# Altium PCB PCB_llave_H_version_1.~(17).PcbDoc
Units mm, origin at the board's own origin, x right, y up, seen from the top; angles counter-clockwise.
Board outline 232.16 x 155.45 mm, 2 copper layers (Top Layer, Bottom Layer); 49 components, 32 nets, 153 pads, 0 vias.
Unrouted connection lines stored in the file: 50.
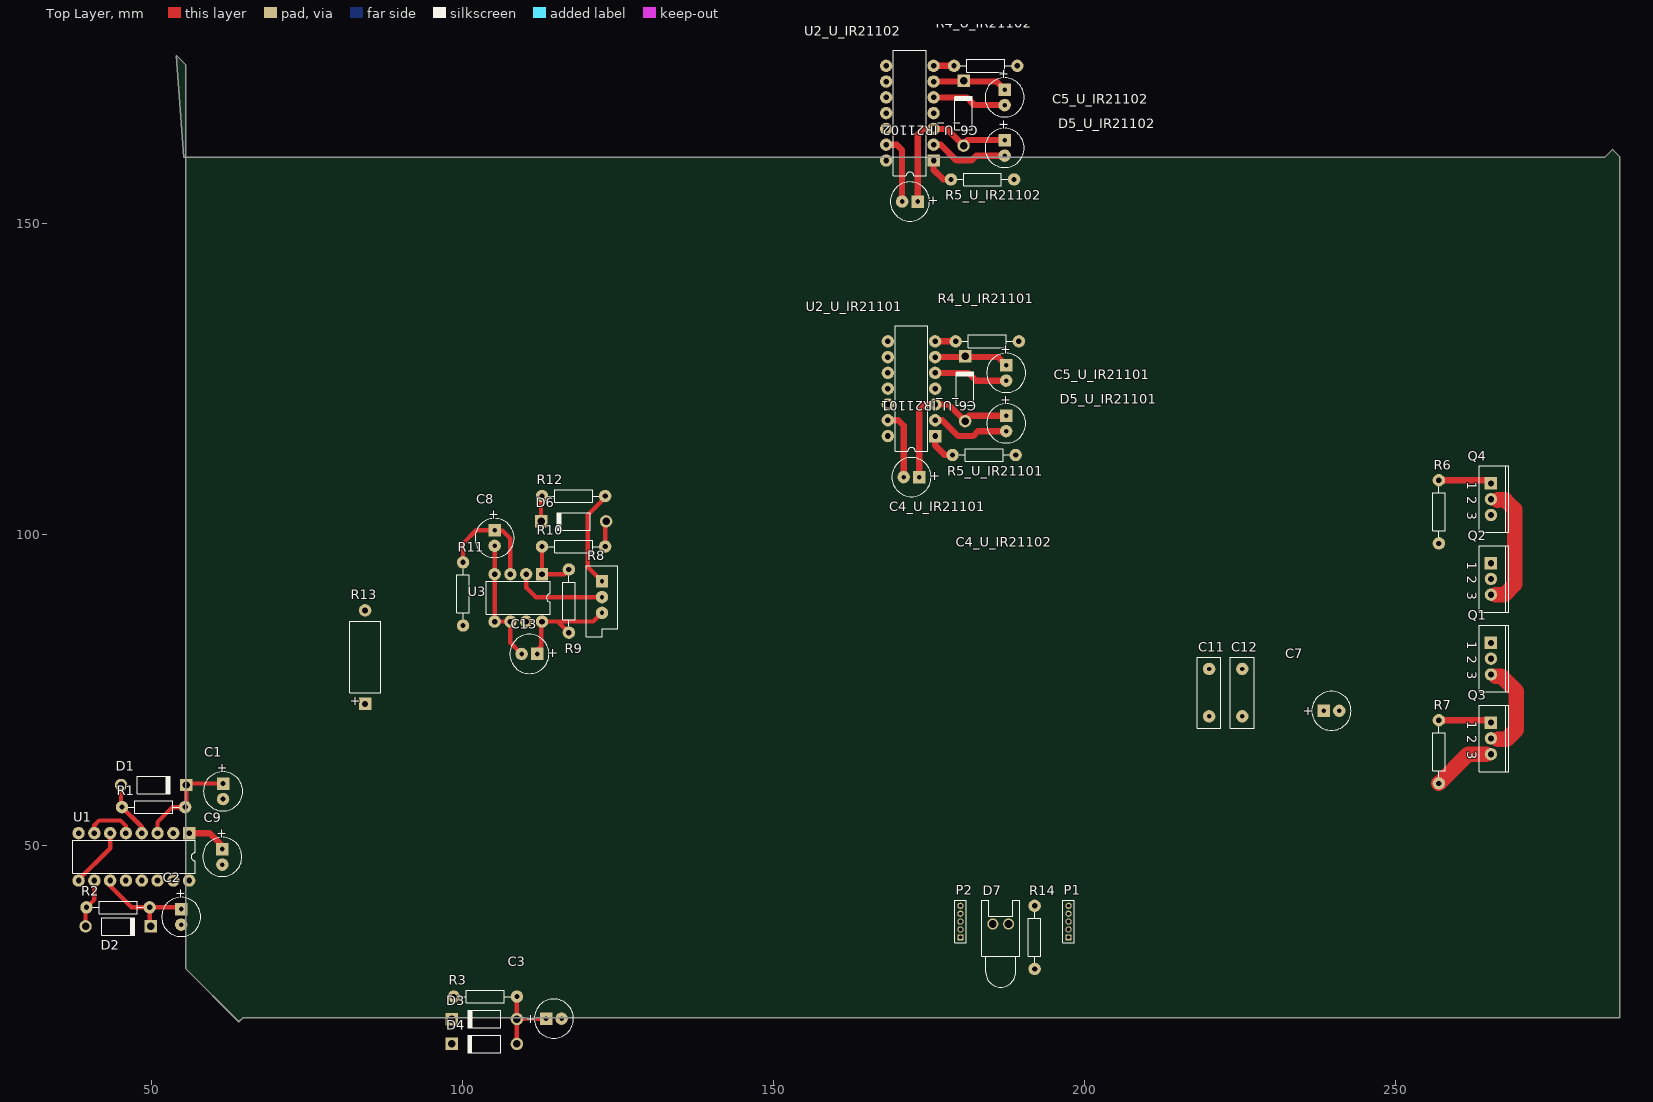
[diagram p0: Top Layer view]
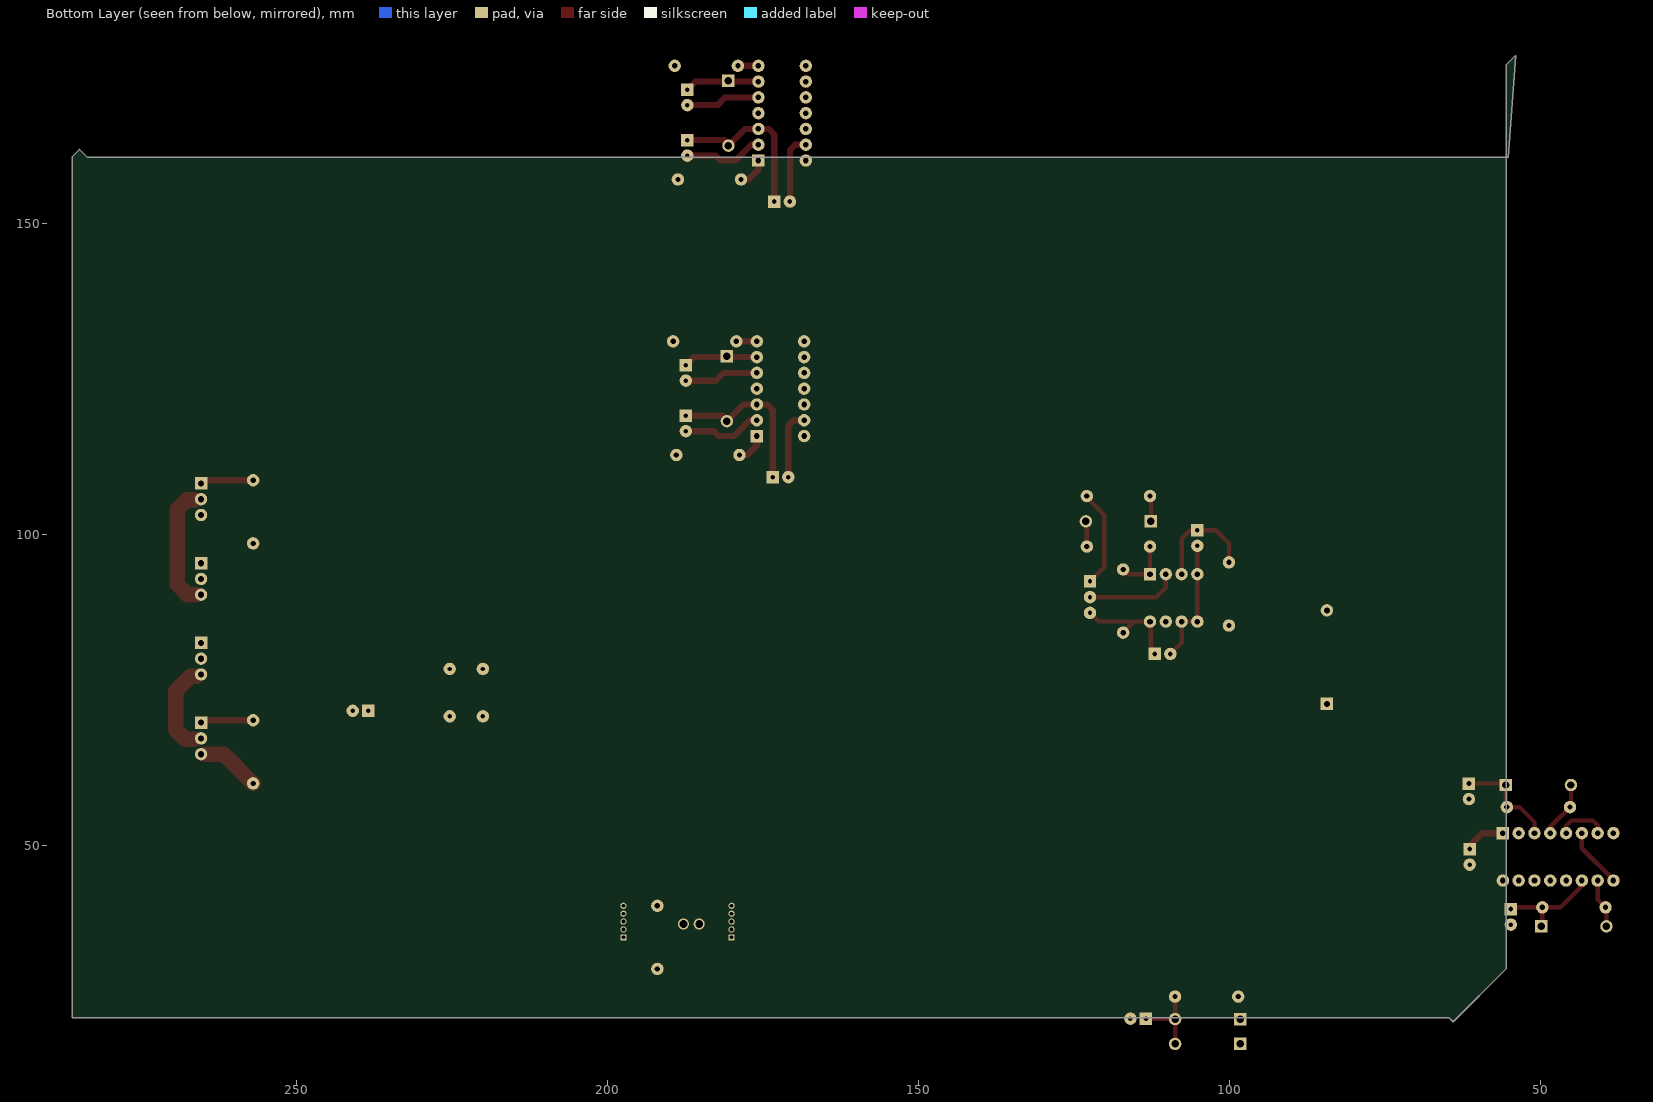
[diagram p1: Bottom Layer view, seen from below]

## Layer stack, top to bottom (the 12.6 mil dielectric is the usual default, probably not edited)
Top Layer: signal copper 0.0356
Dielectric: dielectric 0.32, FR-4, Dk 4.8
Bottom Layer: signal copper 0.0356

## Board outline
53.975,177.038 55.499,175.514 55.499,30.099 64.008,21.59 64.643,22.225 286.131,22.225 286.131,160.782 284.988,161.925 283.718,160.655 55.118,160.655

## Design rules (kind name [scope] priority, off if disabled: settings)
Clearance [All] p1: gap=0.4
ComponentClearance [All] p1: gap=0.254 collisioncheckmode=2 verticalgap=0.254
PolygonConnect [All] p1: connectstyle=Relief reliefconductorwidth=0.254 reliefentries=4 polygonreliefangle="90 Angle"
RoomDefinition U_IR21102 [InComponentClass('U_IR21102')] p1: confinementstyle=ConfineIn formatcopy=TRUE lockcomponents=FALSE outline 164.846,185.293 191.643,185.293 191.643,145.161 164.846,145.161
RoomDefinition U_INITShutdown [InComponentClass('U_INITShutdown')] p2: confinementstyle=ConfineIn formatcopy=TRUE lockcomponents=FALSE outline 90.297,32.893 141.097,32.893 141.097,13.97 90.297,13.97
RoomDefinition U_Shutdown [InComponentClass('U_Shutdown')] p3: confinementstyle=ConfineOut formatcopy=TRUE lockcomponents=FALSE outline 65.913,145.923 116.713,145.923 116.713,121.92 65.913,121.92
RoomDefinition Llave_H_esquema [InComponentClass('Llave_H_esquema')] p4: confinementstyle=ConfineIn formatcopy=TRUE lockcomponents=FALSE outline 178.943,26.924 199.263,26.924 199.263,43.942 178.943,43.942
RoomDefinition U_4049 [InComponentClass('U_4049')] p5: confinementstyle=ConfineIn formatcopy=TRUE lockcomponents=FALSE outline 27.813,33.147 69.469,33.147 69.469,65.913 27.813,65.913
RoomDefinition U_IR21101 [InComponentClass('U_IR21101')] p6: confinementstyle=ConfineIn formatcopy=TRUE lockcomponents=FALSE outline 165.1,140.97 191.897,140.97 191.897,100.838 165.1,100.838
RoomDefinition U_Puente_H [InComponentClass('U_Puente_H')] p7: confinementstyle=ConfineOut formatcopy=TRUE lockcomponents=FALSE outline 178.943,93.853 183.134,93.853 183.134,85.09 178.943,85.09
RoutingVias [All] p1: holewidth=0.711 width=1.27 viastyle="Through Hole" minholewidth=0.711 minwidth=1.27 maxholewidth=0.711 maxwidth=1.27
SolderMaskExpansion [All] p1: expansion=0.102
TestPointUsage [All] p1: valid=0 allowmultiple=FALSE
Testpoint [All] p1: side=15 testpointundercomponent=TRUE minsize=1.016 maxsize=2.54 preferedsize=1.524 minholesize=0 maxholesize=1.016 preferedholesize=0.813 testpointgrid=0.025 style=1023 order=0-112345678
Width [All] p1: maxlimit=3 minlimit=0.7 preferedwidth=1
18 further rules are at their usual default settings.

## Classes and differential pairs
component class U_INITShutdown: C3 D3 D4 R3
channel class IR2110: U_IR21101 U_IR21102
component class U_Shutdown: C8 C13 D6 R8 R9 R10 R11 R12 R13 U3
component class U_Puente_H: C7 C11 C12 Q1 Q2 Q3 Q4 R6 R7
component class U_IR21102: C4_U_IR21102 C5_U_IR21102 C6_U_IR21102 D5_U_IR21102 R4_U_IR21102 R5_U_IR21102 U2_U_IR21102
component class U_IR21101: C4_U_IR21101 C5_U_IR21101 C6_U_IR21101 D5_U_IR21101 R4_U_IR21101 R5_U_IR21101 U2_U_IR21101
component class U_4049: C1 C2 C9 D1 D2 R1 R2 U1
component class Llave_H_esquema: D7 P1 P2 R14

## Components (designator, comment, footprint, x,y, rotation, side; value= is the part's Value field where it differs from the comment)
C1 "Cap Pol1" CAPPR2.5-6.3X5 61.468,58.674 r270 top
C2 "Cap Pol1" CAPPR2.5-6.3X5 54.737,38.481 r270 top
C3 "Cap Pol1" CAPPR2.5-6.3X5 114.681,22.098 r0 top
C4_U_IR21101 "Cap Pol1" CAPPR2.5-6.3X5 172.212,109.22 r180 top (schematic designator C4)
C4_U_IR21102 "Cap Pol1" CAPPR2.5-6.3X5 171.958,153.543 r180 top (schematic designator C4)
C5_U_IR21101 "Cap Pol1" CAPPR2.5-6.3X5 187.452,125.984 r270 top (schematic designator C5)
C5_U_IR21102 "Cap Pol1" CAPPR2.5-6.3X5 187.198,170.307 r270 top (schematic designator C5)
C6_U_IR21101 "Cap Pol1" CAPPR2.5-6.3X5 187.452,117.856 r270 top (schematic designator C6)
C6_U_IR21102 "Cap Pol1" CAPPR2.5-6.3X5 187.198,162.179 r270 top (schematic designator C6)
C7 "Cap Pol1" CAPPR2.5-6.3X5 239.776,71.628 r0 top
C8 "Cap Pol1" CAPPR2.5-6.3X5 105.156,99.421 r270 top
C9 "Cap Pol1" CAPPR2.5-6.3X5 61.341,48.133 r270 top
C11 "Cap" RAD-0.3 220.091,74.549 r90 top
C12 "Cap" RAD-0.3 225.425,74.549 r90 top
C13 "Cap Pol1" CAPPR2.5-6.3X5 110.744,80.772 r180 top
D1 "Diode" DO-204AL 50.292,59.69 r0 top
D2 "Diode" DO-204AL 44.577,36.957 r0 top
D3 "Diode" DO-204AL 103.505,22.036 r180 top
D4 "Diode" DO-204AL 103.505,18.034 r180 top
D5_U_IR21101 "Diode" DO-204AL 180.848,123.444 r90 top (schematic designator D5)
D5_U_IR21102 "Diode" DO-204AL 180.594,167.767 r90 top (schematic designator D5)
D6 "Diode" DO-204AL 117.856,102.108 r180 top
D7 "LED0" LED-0 186.563,37.338 r0 top
P1 "MHDR1X5" MHDR1X5 197.485,35.179 r90 top
P2 "MHDR1X5" MHDR1X5 180.086,35.179 r90 top
Q1 "IRF3205" TO-220AB 265.43,80.01 r270 top
Q2 "IRF3205" TO-220AB 265.43,92.837 r270 top
Q3 "IRF3205" TO-220AB 265.43,67.183 r270 top
Q4 "IRF3205" TO-220AB 265.43,105.664 r270 top
R1 "Res2" AXIAL-0.4 50.292,56.134 r180 top
R2 "Res2" AXIAL-0.4 44.577,40.005 r0 top
R3 "Res2" AXIAL-0.4 103.661,25.654 r180 top
R4_U_IR21101 "Res2" AXIAL-0.4 184.404,131.064 r0 top (schematic designator R4)
R4_U_IR21102 "Res2" AXIAL-0.4 184.15,175.387 r0 top (schematic designator R4)
R5_U_IR21101 "Res2" AXIAL-0.4 183.896,112.776 r0 top (schematic designator R5)
R5_U_IR21102 "Res2" AXIAL-0.4 183.642,157.099 r0 top (schematic designator R5)
R6 "Res2" AXIAL-0.4 257.048,103.632 r90 top
R7 "Res2" AXIAL-0.4 257.048,65.024 r90 top
R8 "RPot" VR5 122.428,89.916 r270 top
R9 "Res2" AXIAL-0.4 117.094,89.281 r270 top
R10 "Res2" AXIAL-0.4 117.856,98.044 r0 top
R11 "Res2" AXIAL-0.4 100.076,90.424 r90 top
R12 "Res2" AXIAL-0.4 117.856,106.172 r180 top
R13 "Res2" CAPPA15.05-11.5x5 84.328,80.264 r90 top
R14 "Res2" AXIAL-0.4 192.024,35.179 r90 top
U1 "MC54HC4049J" 620-09 47.117,48.133 r180 top
U2_U_IR21101 "IR2110" PDIP14 172.212,123.444 r90 top (schematic designator U2)
U2_U_IR21102 "IR2110" PDIP14 171.958,167.767 r90 top (schematic designator U2)
U3 "LM393N" 626-05 108.966,89.789 r180 top

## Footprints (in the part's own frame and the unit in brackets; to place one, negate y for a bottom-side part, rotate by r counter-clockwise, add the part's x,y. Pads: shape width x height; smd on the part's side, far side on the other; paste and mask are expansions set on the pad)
620-09 [mm] "DIP; 16 Leads; Row Spacing 7.62 mm; Pitch 2.54 mm"
  rect 2x2 hole 0.9: 1(-8.89,-3.81)
  round 2 hole 0.9: 2(-6.35,-3.81) 3(-3.81,-3.81) 4(-1.27,-3.81) 5(1.27,-3.81) 6(3.81,-3.81) 7(6.35,-3.81) 8(8.89,-3.81) 9(8.89,3.81) 10(6.35,3.81) 11(3.81,3.81) 12(1.27,3.81) 13(-1.27,3.81) 14(-3.81,3.81) 15(-6.35,3.81) 16(-8.89,3.81)
  silkscreen extent -9.85,-2.65 9.85,2.65
626-05 [mm] "DIP; 8 Leads; Row Spacing 7.62 mm; Pitch 2.54 mm"
  rect 2x2 hole 0.9: 1(-3.81,-3.81)
  round 2 hole 0.9: 2(-1.27,-3.81) 3(1.27,-3.81) 4(3.81,-3.81) 5(3.81,3.81) 6(1.27,3.81) 7(-1.27,3.81) 8(-3.81,3.81)
  silkscreen extent -5.15,-2.65 5.15,2.65
AXIAL-0.4 [mm] "Resistor; 2 Leads"
  round 2 hole 0.85: 1(-5.08,0) 2(5.08,0)
  silkscreen extent -4.06,-1.02 4.06,1.02
CAPPA15.05-11.5x5 [mm] "Capacitor, Electrolytic, Axial; Body 11.5 x 5 mm (LxDia. max), Lead Dia. 0.6 mm (typ)"
  rect 2x2 hole 0.95: 1(-7.525,0)
  round 2 hole 0.95: 2(7.525,0)
  silkscreen extent -5.75,-2.5 5.75,2.5
CAPPR2.5-6.3X5 [mm] "Capacitor, Electrolytic, Radial; Body 6.3 x 5 mm (Dia.xH typ); Pin Spacing 2.5 mm (typ)"
  rect 2x2 hole 0.75: 1(-1.25,0)
  round 2 hole 0.75: 2(1.25,0)
  silkscreen extent -3.15,-3.15 3.15,3.15
DO-204AL [mm] "Diode, Axial; Body 5.2 x 2.7 mm (LxDia. max), Lead Dia. 0.86 mm (max)"
  round 2 hole 1.2: 1(-5.23,0)
  rect 2x2 hole 1.2: 2(5.23,0)
  silkscreen extent -2.65,-1.4 2.75,1.4
LED-0 [mil] "Typical INFRARED GaAs LED; 2 Leads"
  round 70 hole 50: 1(50,0) 2(-50,0)
  silkscreen extent -120,-400 120,150
MHDR1X5 [mm] "Connector; Header; 5 Position"
  rect 1x1 hole 0.6: 1(0,0)
  round 1 hole 0.6: 2(1.27,0) 3(2.54,0) 4(3.81,0) 5(5.08,0)
  silkscreen extent -0.9,-0.9 5.98,0.9
PDIP14 [mm] "DIP; 14 Leads; Row Spacing 7.62 mm; Pitch 2.54 mm"
  rect 2x2 hole 0.9: 1(-7.62,-3.81)
  round 2 hole 0.9: 2(-5.08,-3.81) 3(-2.54,-3.81) 4(0,-3.81) 5(2.54,-3.81) 6(5.08,-3.81) 7(7.62,-3.81) 8(7.62,3.81) 9(5.08,3.81) 10(2.54,3.81) 11(0,3.81) 12(-2.54,3.81) 13(-5.08,3.81) 14(-7.62,3.81)
  silkscreen extent -10.1,-2.65 10.1,2.65
RAD-0.3 [mm] "Capacitor; 2 Leads"
  round 2 hole 0.7: 1(-3.81,0) 2(3.81,0)
  silkscreen extent -5.71,-1.91 5.71,1.91
TO-220AB [mm] "TO, Thru-Hole, Vertical, Heatsink Mounted; 3 In-Line Leads; Pitch 2.54 mm"
  rect 2x2 hole 1: 1(-2.54,0)
  round 2 hole 1: 2(0,0) 3(2.54,0)
  silkscreen extent -5.35,-1.85 5.35,2.85
VR5 [mm] "Potentiometer; 3 Leads"
  rect 2x2 hole 0.7: 1(-2.54,0)
  round 2 hole 0.7: 2(2.54,0) 3(0,0)
  silkscreen extent -5.08,-2.54 6.35,2.54

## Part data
C1 C2 C3 C4_U_IR21101 C4_U_IR21102 C5_U_IR21101 C5_U_IR21102 C6_U_IR21101 C6_U_IR21102 C7 C8 C9 C13: "Polarized Capacitor (Radial)"
C11 C12: "Capacitor"
D1 D2 D3 D4 D5_U_IR21101 D5_U_IR21102 D6: "Default Diode"
D7: "Typical INFRARED GaAs LED"
P1 P2: "Header, 5-Pin"
Q1 Q2 Q3 Q4: "HEXFET Power MOSFET"
R1 R2 R3 R4_U_IR21101 R4_U_IR21102 R5_U_IR21101 R5_U_IR21102 R6 R7 R9 R10 R11 R12 R13 R14: "Resistor"
R8: "Potentiometer"
U1: "Hex Inverting Buffer/Logic-Level Down Converter"
U2_U_IR21101 U2_U_IR21102: "High and Low Side Driver"
U3: "Dual Comparator"

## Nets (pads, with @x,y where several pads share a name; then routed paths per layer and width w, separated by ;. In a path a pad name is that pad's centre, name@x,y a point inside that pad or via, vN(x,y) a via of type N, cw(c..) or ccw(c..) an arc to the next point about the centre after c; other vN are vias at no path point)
COM_U_IR21101: C6_U_IR21101.2 C6_U_IR21102.2 Q3.3 Q4.3 R6.1 R7.1 R11.1 R13.2 U2_U_IR21101.2 U2_U_IR21102.2 | length 35.2
  Top Layer w1: U2_U_IR21102.2 176.911,162.687 179.451,160.147 181.864,160.147 182.646,160.929 C6_U_IR21102.2 ; U2_U_IR21101.2 177.165,118.364 179.705,115.824 182.118,115.824 182.9,116.606 C6_U_IR21101.2
  Top Layer w2.5: R7.1 261.747,64.643 Q3.3@264.668,64.643
GND: C1.2 C2.2 C3.2 C4_U_IR21101.2 C4_U_IR21102.2 C7.2 C8.2 C9.2 C11.1 C12.1 C13.2 D7.2 P1.1 P2.4 R8.1 R12.1 R13.1 U1.8 U2_U_IR21101.13 U2_U_IR21102.13 U3.4 U3.5 U3.6 | length 61.7
  Top Layer w0.7: U3.5 U3.5@105.176,85.999 ; C8.2 105.156,86.019 U3.5@105.176,85.999 ; C13.2 107.696,82.57 U3.6 107.676,85.999 U3.5@105.176,85.999 ; R8.1 120.142,94.742 120.142,103.124 122.936,105.918 R12.1 ; U2_U_IR21102.13 169.545,162.687 ; U2_U_IR21101.13 169.799,118.364
  Top Layer w1: U2_U_IR21102.13 169.839,162.687 170.708,161.818 C4_U_IR21102.2 ; U2_U_IR21101.13 170.093,118.364 170.962,117.495 C4_U_IR21101.2
HIN_U_IR21101: U1.12 U2_U_IR21101.10 U2_U_IR21102.12
HIN_U_IR21102: U1.2 U2_U_IR21101.12 U2_U_IR21102.10
HO1: Q2.1 R4_U_IR21102.2
HO2: Q1.1 R4_U_IR21101.2
IN_SD: D4.2 P2.3
LO1: Q4.1 R5_U_IR21102.2 R6.2 | length 8.6
  Top Layer w1: R6.2 264.922,108.712 Q4.1
LO2: Q3.1 R5_U_IR21101.2 R7.2 | length 8.5
  Top Layer w1: R7.2 265.049,70.104 Q3.1
MOTOR+: C5_U_IR21102.2 Q2.3 Q4.2 U2_U_IR21102.5 | length 31.1
  Top Layer w1: U2_U_IR21102.5 181.102,170.307 182.352,169.057 C5_U_IR21102.2
  Top Layer w2.5: Q2.3@266.192,90.297 267.589,90.297 269.24,91.948 269.24,104.013 267.699,105.554 266.556,105.554 ; 266.525,105.537 266.556,105.537
MOTOR-: C5_U_IR21101.2 Q1.3 Q3.2 U2_U_IR21101.5 | length 26.1
  Top Layer w1: U2_U_IR21101.5 181.356,125.984 182.606,124.734 C5_U_IR21101.2
  Top Layer w2.5: Q1.3@266.192,77.216 267.081,77.216 269.494,74.803 269.494,68.58 267.97,67.056 266.525,67.056
NetC1_1: C1.1 D1.2 R1.1 U1.3 | length 16.9
  Top Layer w0.7: U1.3 50.927,53.721 53.34,56.134 R1.1 55.522,56.284 D1.2 55.756,59.924 C1.1
NetC2_1: C2.1 D2.2 R2.2 U1.11 | length 17
  Top Layer w0.7: U1.11 43.307,43.434 46.736,40.005 54.463,40.005 C2.1 ; R2.2 49.657,37.107 D2.2
NetC3_1: C3.1 D3.1 D4.1 R3.1 | length 12.8
  Top Layer w0.7: D3.1@108.429,22.342 D3.1 113.369,22.036 C3.1 ; D4.1 108.741,18.04 R3.1
NetC5_U_IR21101_1: C5_U_IR21101.1 D5_U_IR21101.2 U2_U_IR21101.6 | length 12.2
  Top Layer w0.7: D5_U_IR21101.2@180.698,128.524 D5_U_IR21101.2
  Top Layer w1: U2_U_IR21101.6 186.162,128.524 C5_U_IR21101.1
NetC5_U_IR21102_1: C5_U_IR21102.1 D5_U_IR21102.2 U2_U_IR21102.6 | length 12.2
  Top Layer w0.7: D5_U_IR21102.2@180.444,172.847 D5_U_IR21102.2
  Top Layer w1: U2_U_IR21102.6 185.908,172.847 C5_U_IR21102.1
NetC8_1: C8.1 R11.2 U3.3 | length 17.8
  Top Layer w0.7: R11.2 100.076,98.552 102.195,100.671 C8.1 105.243,100.584 106.426,100.584 107.696,99.314 U3.3
NetD1_1: D1.1 R1.2 U1.4 | length 9.1
  Top Layer w0.7: D1.1 45.062,56.284 48.387,52.959 U1.4
NetD2_1: D2.1 R2.1 U1.10 | length 8
  Top Layer w0.7: D2.1 39.347,39.855 40.767,41.275 U1.10
NetD6_1: D6.1 R10.2 | length 4.2
  Top Layer w0.7: R10.2 D6.1@122.936,102.235
NetD7_1: D7.1 R14.1
NetR4_U_IR21101_1: R4_U_IR21101.1 U2_U_IR21101.7 | length 3.3
  Top Layer w1: U2_U_IR21101.7 R4_U_IR21101.1
NetR4_U_IR21102_1: R4_U_IR21102.1 U2_U_IR21102.7 | length 3.3
  Top Layer w1: U2_U_IR21102.7 R4_U_IR21102.1
NetR5_U_IR21101_1: R5_U_IR21101.1 U2_U_IR21101.1 | length 4.9
  Top Layer w1: U2_U_IR21101.1 176.022,114.3 177.546,112.776 R5_U_IR21101.1
NetR5_U_IR21102_1: R5_U_IR21102.1 U2_U_IR21102.1 | length 4.9
  Top Layer w1: U2_U_IR21102.1 175.768,158.623 177.292,157.099 R5_U_IR21102.1
NetR8_3: R8.3 U3.2 | length 15
  Top Layer w0.7: U3.2 110.236,91.44 111.76,89.916 R8.3
NetR9_1: R9.1 R10.1 U3.1 | length 9.1
  Top Layer w0.7: R10.1 U3.1 116.332,93.599 R9.1
NetU1_6: U1.6 U1.9 | length 9.7
  Top Layer w0.7: U1.9 38.227,44.45 43.307,49.53 U1.6
PWM: P2.2 U1.5 U1.7 | length 8.2
  Top Layer w0.7: U1.7 40.767,53.213 41.529,53.975 44.958,53.975 45.847,53.086 U1.5
SD: D3.2 D6.2 R12.2 U2_U_IR21101.11 U2_U_IR21102.11 | length 4.1
  Top Layer w0.7: D6.2 112.626,106.022 R12.2
VCC_MOTOR: C7.1 C11.2 C12.2 P1.2 Q1.2 Q2.2
VDD: C4_U_IR21101.1 C4_U_IR21102.1 C6_U_IR21101.1 C6_U_IR21102.1 C9.1 C13.1 D5_U_IR21101.1 D5_U_IR21102.1 P2.5 R3.2 R8.2 R9.2 R14.2 U1.1 U2_U_IR21101.3 U2_U_IR21101.9 U2_U_IR21102.3 U2_U_IR21102.9 U3.8 | length 79.5
  Top Layer w0.7: C9.1 C9.1@61.341,49.784 ; C13.1 111.994,81.387 112.649,82.042 112.649,86.233 112.776,86.106 U3.8 121.031,85.979 R8.2 ; 115.316,85.979 R9.2
  Top Layer w1: U1.1 59.309,51.943 61.341,49.911 C9.1 ; C4_U_IR21102.1 173.208,164.318 174.117,165.227 177.904,165.227 D5_U_IR21102.1 180.594,162.814 181.209,163.429 C6_U_IR21102.1 ; C4_U_IR21101.1 173.462,119.995 174.371,120.904 178.158,120.904 D5_U_IR21101.1 180.848,118.491 181.463,119.106 C6_U_IR21101.1
pads on no net: P1.3 P1.4 P1.5 P2.1 U1.13 U1.14 U1.15 U1.16 U2_U_IR21101.4 U2_U_IR21101.8 U2_U_IR21101.14 U2_U_IR21102.4 U2_U_IR21102.8 U2_U_IR21102.14 U3.7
